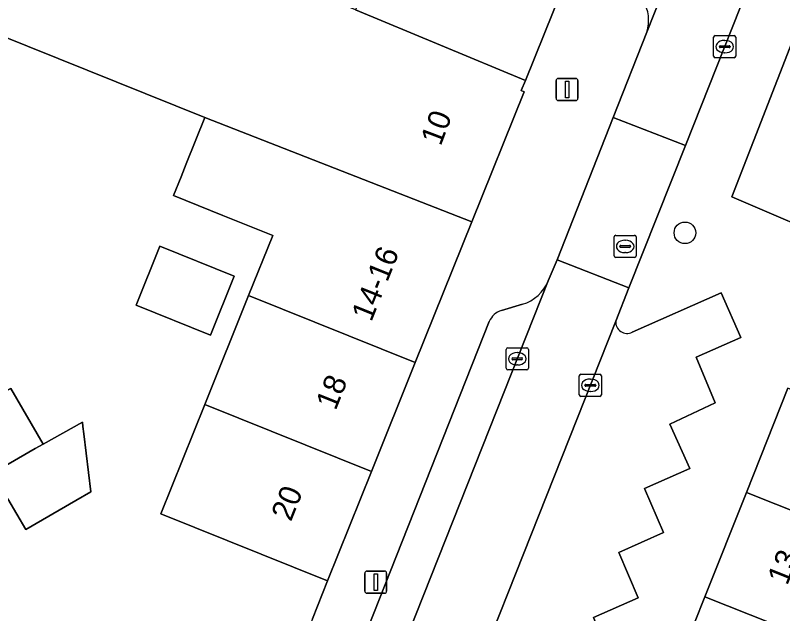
# Model space of a CAD drawing. Extents: x 161798 to 162385, y 382315 to 382833.
# Drawn here: x 162154.49 to 162189.17, y 382559.91 to 382586.96 of the extents above; entities that cross this region are included whole.
import ezdxf

# ---------------------------------------------------------------- set-up
doc = ezdxf.new("R2010")
doc.units = 0
for name, color, linetype in [('IMGEO_Boom', 7, 'Continuous'), ('IMGEO_Erf', 7, 'Continuous'), ('IMGEO_Kolk', 7, 'Continuous'), ('IMGEO_Lichtmast', 7, 'Continuous'), ('IMGEO_Pand', 7, 'Continuous'), ('IMGEO_Pand_nummerreeks', 7, 'Continuous'), ('IMGEO_Parkeervlak_open', 7, 'Continuous'), ('IMGEO_Rijbaan_lokaal_open', 7, 'Continuous'), ('IMGEO_Rioolput', 7, 'Continuous'), ('IMGEO_Voetpad_open', 7, 'Continuous')]:
    doc.layers.add(name, color=color, linetype=linetype)

msp = doc.modelspace()

# ---------------------------------------------------------------- linework, layer by layer
at = {"layer": 'IMGEO_Boom'}
msp.add_circle((162184.752, 382577.129), 0.489, dxfattribs=at)
at = {"layer": 'IMGEO_Erf'}
for points in [[(162167.917, 382559.676), (162168.596, 382561.397), (162161.063, 382564.426), (162163.047, 382569.361), (162165.033, 382574.299), (162166.122, 382577.007), (162165.445, 382577.279), (162163.87, 382577.912), (162161.636, 382578.81), (162161.979, 382579.663), (162162.215, 382580.249), (162163.057, 382582.342), (162153.719, 382586.097)], [(162154.287, 382570.095), (162155.744, 382567.581), (162157.523, 382568.569), (162157.546, 382568.378), (162157.588, 382568.036), (162157.904, 382565.426), (162157.222, 382565.031), (162154.956, 382563.718), (162154.149, 382565.11)]]:
    msp.add_lwpolyline(points, dxfattribs=at)
msp.add_lwpolyline([(162159.945, 382573.856), (162161.018, 382576.523), (162164.376, 382575.172), (162163.302, 382572.504)], close=True, dxfattribs=at)
at = {"layer": 'IMGEO_Kolk'}
for p, q in [((162186.048, 382585.122), (162186.048, 382585.974)), ((162186.123, 382586.048), (162186.975, 382586.048)), ((162187.049, 382585.974), (162187.049, 382585.122)), ((162186.307, 382585.542), (162186.307, 382585.554)), ((162186.35, 382585.591), (162186.748, 382585.591)), ((162186.536, 382585.828), (162186.561, 382585.828)), ((162186.791, 382585.554), (162186.791, 382585.542)), ((162186.745, 382585.505), (162186.347, 382585.505)), ((162186.559, 382585.268), (162186.534, 382585.268)), ((162186.975, 382585.048), (162186.123, 382585.048)), ((162176.674, 382571.008), (162176.674, 382571.86)), ((162176.749, 382571.934), (162177.601, 382571.934)), ((162177.162, 382571.714), (162177.187, 382571.714)), ((162177.675, 382571.86), (162177.675, 382571.008)), ((162176.933, 382571.428), (162176.933, 382571.44)), ((162177.371, 382571.391), (162176.973, 382571.391)), ((162176.976, 382571.477), (162177.374, 382571.477)), ((162177.417, 382571.44), (162177.417, 382571.428)), ((162177.185, 382571.154), (162177.16, 382571.154)), ((162177.601, 382570.934), (162176.749, 382570.934)), ((162179.975, 382569.81), (162179.975, 382570.662)), ((162180.05, 382570.736), (162180.902, 382570.736)), ((162180.976, 382570.662), (162180.976, 382569.81)), ((162180.277, 382570.279), (162180.675, 382570.279)), ((162180.463, 382570.516), (162180.488, 382570.516)), ((162180.234, 382570.23), (162180.234, 382570.242)), ((162180.672, 382570.193), (162180.274, 382570.193)), ((162180.486, 382569.956), (162180.461, 382569.956)), ((162180.718, 382570.242), (162180.718, 382570.23)), ((162180.902, 382569.736), (162180.05, 382569.736))]:
    msp.add_line(p, q, dxfattribs=at)
for points in [[(162186.048, 382585.122), (162186.048, 382585.974)], [(162186.123, 382586.048), (162186.975, 382586.048)], [(162187.049, 382585.974), (162187.049, 382585.122)], [(162186.975, 382585.048), (162186.123, 382585.048)], [(162176.674, 382571.008), (162176.674, 382571.86)], [(162176.749, 382571.934), (162177.601, 382571.934)], [(162177.675, 382571.86), (162177.675, 382571.008)], [(162177.601, 382570.934), (162176.749, 382570.934)], [(162179.975, 382569.81), (162179.975, 382570.662)], [(162180.05, 382570.736), (162180.902, 382570.736)], [(162180.976, 382570.662), (162180.976, 382569.81)], [(162180.902, 382569.736), (162180.05, 382569.736)]]:
    msp.add_lwpolyline(points, dxfattribs=at)
for centre, radius, start, end in [((162186.125, 382585.972), 0.0765, 91.552, 178.448), ((162186.125, 382585.972), 0.0765, 91.552, 178.448), ((162186.973, 382585.972), 0.0765, 1.552, 88.448), ((162186.973, 382585.972), 0.0765, 1.552, 88.448), ((162186.347, 382585.551), 0.0403, 85.8775, 175.7526), ((162186.344, 382585.541), 0.0366, 178.938, 274.7102), ((162186.748, 382585.548), 0.043, 264.8664, 352.4533), ((162186.752, 382585.553), 0.0386, 1.7309, 96.639), ((162186.125, 382585.124), 0.0765, 181.552, 268.448), ((162186.125, 382585.124), 0.0765, 181.552, 268.448), ((162186.973, 382585.124), 0.0765, 271.552, 358.448), ((162186.973, 382585.124), 0.0765, 271.552, 358.448), ((162176.751, 382571.858), 0.0765, 91.552, 178.448), ((162176.751, 382571.858), 0.0765, 91.552, 178.448), ((162177.599, 382571.858), 0.0765, 1.552, 88.448), ((162177.599, 382571.858), 0.0765, 1.552, 88.448), ((162176.973, 382571.437), 0.0403, 85.8775, 175.7526), ((162176.97, 382571.427), 0.0366, 178.938, 274.7102), ((162177.374, 382571.434), 0.043, 264.8664, 352.4533), ((162177.378, 382571.439), 0.0386, 1.7309, 96.639), ((162176.751, 382571.01), 0.0765, 181.552, 268.448), ((162176.751, 382571.01), 0.0765, 181.552, 268.448), ((162177.599, 382571.01), 0.0765, 271.552, 358.448), ((162177.599, 382571.01), 0.0765, 271.552, 358.448), ((162180.052, 382570.66), 0.0765, 91.552, 178.448), ((162180.052, 382570.66), 0.0765, 91.552, 178.448), ((162180.9, 382570.66), 0.0765, 1.552, 88.448), ((162180.9, 382570.66), 0.0765, 1.552, 88.448), ((162180.274, 382570.239), 0.0403, 85.8775, 175.7526), ((162180.679, 382570.241), 0.0386, 1.7309, 96.639), ((162180.271, 382570.229), 0.0366, 178.938, 274.7102), ((162180.675, 382570.236), 0.043, 264.8664, 352.4533), ((162180.052, 382569.812), 0.0765, 181.552, 268.448), ((162180.052, 382569.812), 0.0765, 181.552, 268.448), ((162180.9, 382569.812), 0.0765, 271.552, 358.448), ((162180.9, 382569.812), 0.0765, 271.552, 358.448)]:
    msp.add_arc(centre, radius, start, end, dxfattribs=at)
for centre, major_axis, ratio, start_param, end_param in [((162186.535, 382585.548), (-0.387, 0.002), 0.722429, 4.712389, 7.853982), ((162186.56, 382585.548), (-0.39, 0.002), 0.717154, 1.570796, 4.712389), ((162177.161, 382571.434), (-0.387, 0.002), 0.722429, 4.712389, 7.853982), ((162177.186, 382571.434), (-0.39, 0.002), 0.717154, 1.570796, 4.712389), ((162180.462, 382570.236), (-0.387, 0.002), 0.722429, 4.712389, 7.853982), ((162180.487, 382570.236), (-0.39, 0.002), 0.717154, 1.570796, 4.712389)]:
    msp.add_ellipse(centre, major_axis=major_axis, ratio=ratio, start_param=start_param, end_param=end_param, dxfattribs=at)
at = {"layer": 'IMGEO_Lichtmast'}
for p, q in [((162178.927, 382583.211), (162178.927, 382584.011)), ((162178.927, 382584.011), (162178.927, 382583.211)), ((162179.027, 382584.111), (162179.817, 382584.111)), ((162179.817, 382584.111), (162179.027, 382584.111)), ((162179.917, 382584.011), (162179.917, 382583.211)), ((162179.917, 382583.211), (162179.917, 382584.011)), ((162179.817, 382583.111), (162179.027, 382583.111)), ((162179.027, 382583.111), (162179.817, 382583.111)), ((162170.28, 382560.934), (162170.28, 382561.734)), ((162170.28, 382561.734), (162170.28, 382560.934)), ((162170.38, 382561.834), (162171.17, 382561.834)), ((162171.17, 382561.834), (162170.38, 382561.834)), ((162171.27, 382561.734), (162171.27, 382560.934)), ((162171.27, 382560.934), (162171.27, 382561.734)), ((162171.17, 382560.834), (162170.38, 382560.834)), ((162170.38, 382560.834), (162171.17, 382560.834))]:
    msp.add_line(p, q, dxfattribs=at)
for points in [[(162179.347, 382583.986), (162179.497, 382583.986), (162179.497, 382583.236), (162179.347, 382583.236), (162179.347, 382583.986)], [(162170.7, 382561.709), (162170.85, 382561.709), (162170.85, 382560.959), (162170.7, 382560.959), (162170.7, 382561.709)]]:
    msp.add_lwpolyline(points, dxfattribs=at)
for centre, start, end in [((162179.027, 382584.011), 90, 180), ((162179.027, 382584.011), 90, 180), ((162179.817, 382584.011), 0, 90), ((162179.817, 382584.011), 360, 90), ((162179.027, 382583.211), 180, 270), ((162179.027, 382583.211), 180, 270), ((162179.817, 382583.211), 270, 0), ((162179.817, 382583.211), 270, 0), ((162170.38, 382561.734), 90, 180), ((162170.38, 382561.734), 90, 180), ((162171.17, 382561.734), 0, 90), ((162171.17, 382561.734), 360, 90), ((162170.38, 382560.934), 180, 270), ((162170.38, 382560.934), 180, 270), ((162171.17, 382560.934), 270, 0), ((162171.17, 382560.934), 270, 0)]:
    msp.add_arc(centre, 0.1, start, end, dxfattribs=at)
at = {"layer": 'IMGEO_Pand'}
for points in [[(162169.858, 382587.213), (162177.539, 382584.02), (162179.636, 382589.236), (162165.808, 382594.796), (162164.617, 382591.834), (162170.728, 382589.376)], [(162169.858, 382587.213), (162153.17, 382593.924), (162152.432, 382592.088), (162153.719, 382586.097), (162163.057, 382582.342), (162175.121, 382577.623), (162177.487, 382583.507), (162177.354, 382583.56), (162177.539, 382584.02)], [(162202.18, 382579.336), (162203.015, 382581.474), (162202.76, 382581.579), (162199.819, 382582.722), (162197.912, 382583.464), (162189.907, 382586.575), (162186.87, 382578.758), (162192.01, 382576.554), (162192.384, 382576.394), (162193.08, 382578.017), (162193.239, 382578.387), (162193.297, 382578.521), (162198.066, 382576.668), (162199.507, 382580.375), (162201.962, 382579.421)], [(162175.121, 382577.623), (162163.057, 382582.342), (162162.215, 382580.249), (162161.979, 382579.663), (162161.636, 382578.81), (162163.87, 382577.912), (162165.445, 382577.279), (162166.122, 382577.007), (162165.033, 382574.299), (162172.565, 382571.268)], [(162159.945, 382573.856), (162163.302, 382572.504), (162164.376, 382575.172), (162161.018, 382576.523)], [(162165.033, 382574.299), (162163.047, 382569.361), (162170.58, 382566.332), (162172.565, 382571.268)], [(162155.744, 382567.581), (162154.287, 382570.095), (162152.029, 382568.786), (162150.157, 382567.66), (162149.096, 382567.046), (162147.528, 382569.752), (162139.909, 382565.336), (162142.917, 382560.146), (162155.383, 382567.372)], [(162195.638, 382562.163), (162195.705, 382562.331), (162199.185, 382561.806), (162200.68, 382565.566), (162197.495, 382566.833), (162189.401, 382570.101), (162187.527, 382565.389)], [(162170.58, 382566.332), (162163.047, 382569.361), (162161.063, 382564.426), (162168.596, 382561.397)], [(162155.744, 382567.581), (162155.383, 382567.372), (162142.917, 382560.146), (162145.925, 382554.955), (162153.543, 382559.37), (162152.034, 382561.973), (162153.084, 382562.582), (162152.255, 382564.012), (162154.149, 382565.11), (162154.956, 382563.718), (162157.222, 382565.031), (162157.904, 382565.426), (162157.588, 382568.036), (162157.546, 382568.378), (162157.523, 382568.569)], [(162195.638, 382562.163), (162187.527, 382565.389), (162185.652, 382560.677), (162193.763, 382557.45)], [(162193.763, 382557.45), (162185.652, 382560.677), (162183.777, 382555.964), (162191.889, 382552.738)]]:
    msp.add_lwpolyline(points, close=True, dxfattribs=at)
at = {"layer": 'IMGEO_Parkeervlak_open'}
for points in [[(162183.036, 382586.209), (162196.606, 382620.511)], [(162170.621, 382554.892), (162178.575, 382574.96)], [(162172.902, 382548.953), (162179.247, 382551.849), (162178.3, 382553.854), (162180.323, 382554.783), (162179.444, 382556.811), (162181.471, 382557.698), (162180.621, 382559.742), (162182.642, 382560.634), (162181.758, 382562.683), (162183.78, 382563.584), (162182.929, 382565.575), (162184.969, 382566.473), (162184.061, 382568.472), (162186.115, 382569.439), (162185.253, 382571.505), (162187.28, 382572.39), (162186.384, 382574.415), (162182.369, 382572.638)], [(162177.412, 382573.901), (162176.46, 382573.621)], [(162175.91, 382573.119), (162169.897, 382557.907)], [(162181.625, 382573.137), (162171.513, 382547.64)]]:
    msp.add_lwpolyline(points, dxfattribs=at)
for centre, radius, start, end in [((162181.266, 382586.724), 1.843, 343.7893, 29.4573), ((162176.891, 382575.641), 1.816, 286.662, 337.9785), ((162176.702, 382572.804), 0.852, 106.4828, 158.2923), ((162182.137, 382573.097), 0.514, 175.5095, 296.7911)]:
    msp.add_arc(centre, radius, start, end, dxfattribs=at)
at = {"layer": 'IMGEO_Rijbaan_lokaal_open'}
for points in [[(162193.938, 382604.183), (162196.082, 382609.705), (162197.87, 382614.249), (162197.933, 382614.428), (162200.724, 382621.462), (162201.9, 382624.403), (162198.611, 382625.691), (162198.183, 382624.669), (162196.606, 382620.511), (162183.036, 382586.209), (162181.51, 382582.342), (162184.773, 382581.075), (162192.527, 382600.624)], [(162184.773, 382581.075), (162181.51, 382582.342), (162178.971, 382575.905), (162182.222, 382574.642)], [(162166.587, 382535.18), (162171.513, 382547.64), (162181.625, 382573.137), (162182.222, 382574.642), (162178.971, 382575.905), (162178.575, 382574.96), (162170.621, 382554.892), (162170.585, 382554.784), (162170.508, 382554.627), (162164.884, 382540.483), (162163.254, 382536.338)]]:
    msp.add_lwpolyline(points, close=True, dxfattribs=at)
at = {"layer": 'IMGEO_Rioolput'}
for p, q in [((162181.551, 382576.09), (162181.551, 382576.942)), ((162181.626, 382577.016), (162182.478, 382577.016)), ((162182.552, 382576.942), (162182.552, 382576.09)), ((162181.81, 382576.51), (162181.81, 382576.522)), ((162181.853, 382576.559), (162182.251, 382576.559)), ((162182.039, 382576.796), (162182.064, 382576.796)), ((162182.294, 382576.522), (162182.294, 382576.51)), ((162182.248, 382576.473), (162181.85, 382576.473)), ((162182.062, 382576.236), (162182.037, 382576.236)), ((162182.478, 382576.016), (162181.626, 382576.016))]:
    msp.add_line(p, q, dxfattribs=at)
for points in [[(162181.551, 382576.09), (162181.551, 382576.942)], [(162181.626, 382577.016), (162182.478, 382577.016)], [(162182.552, 382576.942), (162182.552, 382576.09)], [(162182.478, 382576.016), (162181.626, 382576.016)]]:
    msp.add_lwpolyline(points, dxfattribs=at)
for centre, radius, start, end in [((162181.628, 382576.94), 0.0765, 91.552, 178.448), ((162181.628, 382576.94), 0.0765, 91.552, 178.448), ((162182.476, 382576.94), 0.0765, 1.552, 88.448), ((162182.476, 382576.94), 0.0765, 1.552, 88.448), ((162181.85, 382576.519), 0.0403, 85.8775, 175.7526), ((162182.255, 382576.521), 0.0386, 1.7309, 96.639), ((162181.847, 382576.509), 0.0366, 178.938, 274.7102), ((162182.251, 382576.516), 0.043, 264.8664, 352.4533), ((162181.628, 382576.092), 0.0765, 181.552, 268.448), ((162181.628, 382576.092), 0.0765, 181.552, 268.448), ((162182.476, 382576.092), 0.0765, 271.552, 358.448), ((162182.476, 382576.092), 0.0765, 271.552, 358.448)]:
    msp.add_arc(centre, radius, start, end, dxfattribs=at)
for centre, major_axis, ratio, start_param, end_param in [((162182.038, 382576.516), (-0.387, 0.002), 0.722429, 4.712389, 7.853982), ((162182.063, 382576.516), (-0.39, 0.002), 0.717154, 1.570796, 4.712389)]:
    msp.add_ellipse(centre, major_axis=major_axis, ratio=ratio, start_param=start_param, end_param=end_param, dxfattribs=at)
at = {"layer": 'IMGEO_Voetpad_open'}
for points in [[(162197.87, 382614.249), (162196.082, 382609.705), (162193.938, 382604.183), (162192.527, 382600.624), (162184.773, 382581.075), (162182.222, 382574.642), (162181.625, 382573.137)], [(162179.636, 382589.236), (162177.539, 382584.02), (162177.354, 382583.56), (162177.487, 382583.507), (162175.121, 382577.623), (162172.565, 382571.268), (162170.58, 382566.332), (162168.596, 382561.397), (162167.917, 382559.676), (162162.021, 382544.742), (162159.046, 382537.334), (162160.799, 382536.612), (162159.178, 382532.372), (162158.702, 382531.126), (162159.29, 382530.901), (162157.63, 382526.559), (162157.208, 382526.721), (162155.498, 382522.248)], [(162192.01, 382576.554), (162186.87, 382578.758), (162189.907, 382586.575)], [(162178.575, 382574.96), (162178.971, 382575.905), (162181.51, 382582.342), (162183.036, 382586.209)], [(162182.369, 382572.638), (162186.384, 382574.415), (162187.28, 382572.39), (162185.253, 382571.505), (162186.115, 382569.439), (162184.061, 382568.472), (162184.969, 382566.473), (162182.929, 382565.575), (162183.78, 382563.584), (162181.758, 382562.683), (162182.642, 382560.634), (162180.621, 382559.742), (162181.471, 382557.698), (162179.444, 382556.811), (162180.323, 382554.783), (162178.3, 382553.854), (162179.247, 382551.849), (162172.902, 382548.953)], [(162176.46, 382573.621), (162177.412, 382573.901)], [(162169.897, 382557.907), (162175.91, 382573.119)], [(162161.842, 382511.712), (162164.027, 382517.204), (162164.322, 382517.949), (162162.703, 382518.511), (162165.279, 382524.987), (162169.14, 382534.691), (162170.627, 382538.431), (162173.318, 382545.194), (162174.656, 382548.553), (162179.984, 382546.428), (162181.903, 382551.252), (162183.777, 382555.964), (162185.652, 382560.677), (162187.527, 382565.389), (162189.401, 382570.101)]]:
    msp.add_lwpolyline(points, dxfattribs=at)
for centre, radius, start, end in [((162181.266, 382586.724), 1.843, 343.7893, 29.4573), ((162176.891, 382575.641), 1.816, 286.662, 337.9785), ((162176.702, 382572.804), 0.852, 106.4828, 158.2923), ((162182.137, 382573.097), 0.514, 175.5095, 296.7911)]:
    msp.add_arc(centre, radius, start, end, dxfattribs=at)

# ---------------------------------------------------------------- texts
at = {"layer": 'IMGEO_Pand_nummerreeks'}
for s, rotation, p in [('10', 69.2939, (162173.712, 382581.022)), ('14-16', 68.096, (162170.575, 382573.072)), ('18', 68.0826, (162168.962, 382569.061)), ('20', 68.0986, (162166.943, 382564.041)), ('13', 68.3075, (162189.373, 382561.155))]:
    msp.add_text(s, height=1, rotation=rotation, dxfattribs=at).set_placement(p)

doc.saveas('drawing.dxf')
